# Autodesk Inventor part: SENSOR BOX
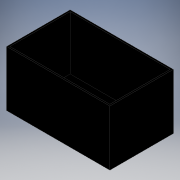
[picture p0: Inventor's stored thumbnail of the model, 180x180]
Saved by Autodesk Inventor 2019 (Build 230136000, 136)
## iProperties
Created: 2021-07
Part Number: SENSOR BOX
Material: Nickel-Copper Alloy 400
Document SubType Name: Modeling
Designer: Avinash
Density: 8.83 g/cm^3
Appearance: Anodized - Black
Author: Avinash
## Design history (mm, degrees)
sketch "Sketch1"
  geometry: L1 (0, 0)-(-130, 0); L2 (-130, 0)-(-130, 70); L3 (-130, 70)-(0, 70); L4 (0, 70)-(0, 0)
  constraints: 8 end point, 2 parallel, 1 horizontal, 1 perpendicular
  dimensions: "d0" = 130 distance of L2.end L3.end; "d1" = 70 distance of L1.end L2.end
extrude "Extrusion1" new body sketch "Sketch1" distance "d2" = 80; taper "d3" = 0 deg
shell "Shell1" dims "d4" = 2
sketch "Sketch2"
  geometry: L1 (0, 0)-(126, 0) reference; L2 (0, -76)-(0, 0) reference; C1 r 29.262 at (35, -38); 1 further point
  constraints: 1 centre point
  dimensions: "d5" = 38 distance from line of L1 C1.centre; "d6" = 35 distance from line of L2 C1.centre
extrude "Extrusion2" cut sketch "Sketch2" distance "d7" = 10; taper "d8" = 0 deg
body "Solid1"
